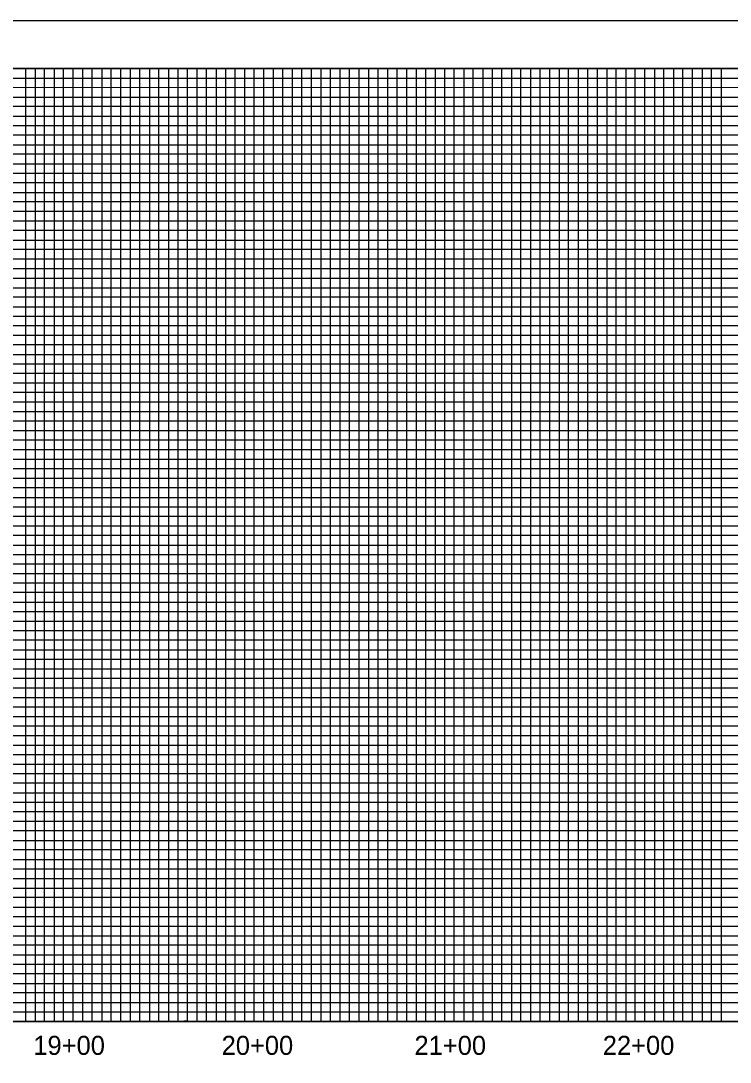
# Model space of a CAD drawing. Extents: x 502400 to 509344, y 448070 to 484209.
# Drawn here: x 506542 to 506914, y 483662 to 484209 of the extents above; entities that cross this region are included whole.
import ezdxf

# ---------------------------------------------------------------- set-up
doc = ezdxf.new("R2010")
doc.units = 0
for name, color, linetype in [('Exist Vertical Profile Vertical Axis Label', 7, 'Continuous'), ('Sheet Layout Profile Border Port 1', 7, 'Continuous'), ('Sheet Plot Border Outside CELL', 7, 'Continuous'), ('Sheet Profile CELL', 7, 'Continuous'), ('Sheet Profile Grid Major CELL', 7, 'Continuous'), ('Sheet Profile Grid Middle CELL', 7, 'Continuous'), ('Sheet Profile Grid Minor CELL', 7, 'Continuous')]:
    doc.layers.add(name, color=color, linetype=linetype)

msp = doc.modelspace()

# ---------------------------------------------------------------- linework, layer by layer
at = {"layer": 'Sheet Layout Profile Border Port 1'}
msp.add_lwpolyline([(506419.08, 484183.71), (507169.08, 484183.71), (507169.08, 483683.71), (506419.08, 483683.71)], close=True, dxfattribs=at)
at = {"layer": 'Sheet Plot Border Outside CELL'}
msp.add_lwpolyline([(505602.08, 483108.71), (507286.08, 483108.71), (507286.08, 484208.71), (505602.08, 484208.71)], close=True, dxfattribs=at)
at = {"layer": 'Sheet Profile CELL'}
msp.add_line((505769.08, 483683.71), (507269.08, 483683.71), dxfattribs=at)
msp.add_lwpolyline([(507269.08, 484183.71), (505769.08, 484183.71), (505769.08, 483133.71), (507269.08, 483133.71)], close=True, dxfattribs=at)
at = {"layer": 'Sheet Profile Grid Major CELL'}
for points in [[(506519.08, 483683.71), (506569.08, 483683.71), (506569.08, 484183.71), (506619.08, 484183.71), (506619.08, 483683.71), (506669.08, 483683.71), (506669.08, 484183.71), (506719.08, 484183.71), (506719.08, 483683.71), (506769.08, 483683.71), (506769.08, 484183.71), (506819.08, 484183.71), (506819.08, 483683.71), (506869.08, 483683.71), (506869.08, 484183.71), (506919.08, 484183.71), (506919.08, 483683.71), (506969.08, 483683.71), (506969.08, 484183.71), (507019.08, 484183.71), (507019.08, 483683.71), (507069.08, 483683.71), (507069.08, 484183.71), (507095.38, 484183.71)], [(505769.08, 484133.71), (507069.08, 484133.71)], [(507069.08, 484083.71), (505769.08, 484083.71), (505769.08, 484033.71), (507069.08, 484033.71)], [(507269.08, 483983.71), (505769.08, 483983.71), (505769.08, 483933.71), (507269.08, 483933.71)], [(507269.08, 483883.71), (505769.08, 483883.71), (505769.08, 483833.71), (507269.08, 483833.71)], [(507269.08, 483783.71), (505769.08, 483783.71), (505769.08, 483783.71), (505769.08, 483733.71), (507269.08, 483733.71)]]:
    msp.add_lwpolyline(points, dxfattribs=at)
at = {"layer": 'Sheet Profile Grid Middle CELL'}
msp.add_line((505769.08, 484158.71), (507069.03, 484158.71), dxfattribs=at)
msp.add_line((505769.08, 484158.71), (507069.03, 484158.71), dxfattribs=at)
for points in [[(506494.08, 484183.71), (506544.08, 484183.71), (506544.08, 483683.71), (506594.08, 483683.71), (506594.08, 484183.71), (506644.08, 484183.71), (506644.08, 483683.71), (506694.08, 483683.71), (506694.08, 484183.71), (506744.08, 484183.71), (506744.08, 483683.71), (506794.08, 483683.71), (506794.08, 484183.71), (506844.08, 484183.71), (506844.08, 483683.71), (506894.08, 483683.71), (506894.08, 484183.71), (506944.08, 484183.71)], [(507069.08, 484108.71), (505769.08, 484108.71), (505769.08, 484058.71), (507069.08, 484058.71)], [(507269.08, 484008.71), (505769.08, 484008.71), (505769.08, 483958.71), (507094.08, 483958.71)], [(507269.08, 483908.71), (505769.08, 483908.71), (505769.08, 483858.71), (507269.08, 483858.71)], [(507269.08, 483808.71), (505769.08, 483808.71), (505769.08, 483758.71), (507269.08, 483758.71)], [(507269.08, 483708.71), (505769.08, 483708.71)]]:
    msp.add_lwpolyline(points, dxfattribs=at)
at = {"layer": 'Sheet Profile Grid Minor CELL'}
for p, q in [((505819.08, 484178.71), (507069.08, 484178.71)), ((507069.08, 484173.71), (505819.08, 484173.36)), ((505819.08, 484168.71), (507069.08, 484168.71)), ((507069.03, 484048.71), (505819.08, 484048.71)), ((507069.08, 484043.71), (505819.08, 484043.71)), ((507069.08, 484038.71), (505819.08, 484038.71)), ((505819.08, 484028.71), (507069.08, 484028.71)), ((507069.08, 484023.71), (505819.08, 484023.71)), ((505819.08, 484018.71), (507219.08, 484018.71)), ((507219.08, 483998.71), (505819.08, 483998.71)), ((505819.08, 483993.71), (507219.08, 483993.71)), ((507219.08, 483973.71), (505819.08, 483973.71)), ((505819.08, 483968.71), (507219.08, 483968.71)), ((507219.08, 483948.71), (505819.08, 483948.71)), ((505819.08, 483943.71), (507219.08, 483943.71)), ((507219.08, 483938.71), (505819.08, 483938.71)), ((505819.08, 483928.71), (507219.08, 483928.71)), ((507219.08, 483923.71), (505819.08, 483923.71)), ((505819.08, 483918.71), (507219.08, 483918.71)), ((507219.08, 483913.71), (505819.08, 483913.71)), ((505819.08, 483903.71), (507219.08, 483903.71)), ((507219.08, 483898.71), (505819.08, 483898.71)), ((505819.08, 483893.71), (507219.08, 483893.71)), ((507219.08, 483888.71), (505819.08, 483888.71)), ((505819.08, 483878.71), (507219.08, 483878.71)), ((507219.08, 483873.71), (505819.08, 483873.71)), ((505819.08, 483868.71), (507219.08, 483868.71)), ((507219.08, 483863.71), (505819.08, 483863.71)), ((505819.08, 483853.71), (507219.08, 483853.71)), ((507219.08, 483848.71), (505819.08, 483848.71)), ((505819.08, 483843.71), (507219.08, 483843.71)), ((507219.08, 483838.71), (505819.08, 483838.71)), ((505819.08, 483828.71), (507219.08, 483828.71)), ((507219.08, 483823.71), (505819.08, 483823.71)), ((505819.08, 483818.71), (507219.08, 483818.71)), ((507219.08, 483813.71), (505819.08, 483813.71)), ((505819.08, 483803.71), (507219.08, 483803.71)), ((507219.08, 483798.71), (505819.08, 483798.71)), ((507219.08, 483793.71), (505819.08, 483793.71)), ((507219.08, 483788.71), (505819.08, 483788.71)), ((505819.08, 483778.71), (507219.08, 483778.71)), ((507219.08, 483773.71), (505819.08, 483773.71)), ((505819.08, 483768.71), (507219.08, 483768.71)), ((507219.08, 483763.71), (505819.08, 483763.71)), ((505819.08, 483753.71), (507219.08, 483753.71)), ((507219.08, 483748.71), (505819.08, 483748.71)), ((505819.08, 483743.71), (507219.08, 483743.71)), ((507219.08, 483738.71), (505819.08, 483738.71)), ((505819.08, 483728.71), (507219.08, 483728.71)), ((507219.08, 483723.71), (505819.08, 483723.71)), ((505819.08, 483718.71), (507219.08, 483718.71)), ((507219.08, 483713.71), (505819.08, 483713.71)), ((505819.08, 483703.71), (507219.08, 483703.71)), ((507219.08, 483698.71), (505819.08, 483698.71)), ((505819.08, 483693.71), (507219.08, 483693.71))]:
    msp.add_line(p, q, dxfattribs=at)
for points in [[(506539.08, 484183.71), (506549.08, 484183.71), (506549.08, 483683.71), (506554.08, 483683.71), (506554.08, 484183.71), (506559.08, 484183.71), (506559.08, 483683.71), (506564.08, 483683.71), (506564.08, 484183.71), (506574.08, 484183.71), (506574.08, 483683.71), (506579.08, 483683.71), (506579.08, 484183.71), (506584.08, 484183.71), (506584.08, 483683.71), (506589.08, 483683.71), (506589.08, 484183.71), (506599.08, 484183.71), (506599.08, 483683.71), (506604.08, 483683.71), (506604.08, 484183.71), (506609.08, 484183.71), (506609.08, 483683.71), (506614.08, 483683.71), (506614.08, 484183.71), (506624.08, 484183.71), (506624.08, 483683.71), (506628.78, 483684.26), (506629.08, 483683.71), (506629.08, 484183.71), (506634.08, 484183.71), (506634.08, 483683.71), (506639.08, 483683.71), (506639.08, 484183.71), (506649.08, 484183.71), (506649.08, 483683.71), (506654.08, 483683.71)], [(506654.08, 483683.71), (506654.08, 484183.71), (506659.08, 484183.71), (506659.08, 483683.71), (506664.08, 483683.71), (506664.08, 484183.71), (506674.08, 484183.71), (506674.08, 483683.71), (506679.08, 483683.71), (506679.08, 484183.71), (506684.08, 484183.71), (506684.08, 483683.71), (506689.08, 483683.71), (506689.08, 484183.71), (506699.08, 484183.71), (506699.08, 483683.71), (506704.08, 483683.71), (506704.08, 484183.71), (506709.08, 484183.71), (506709.08, 483683.71), (506714.08, 483683.71), (506714.08, 484183.71), (506724.08, 484183.71), (506724.08, 483683.71), (506729.08, 483683.71), (506729.08, 484183.71), (506734.08, 484183.71), (506734.08, 483683.71), (506739.08, 483683.71), (506739.08, 484183.71), (506749.08, 484183.71), (506749.08, 483683.71), (506754.08, 483683.71), (506754.08, 484183.71), (506759.08, 484183.71), (506759.08, 483683.71), (506764.08, 483683.71), (506764.08, 484183.71), (506774.08, 484183.71), (506774.08, 483683.71), (506779.08, 483683.71), (506779.08, 484183.71), (506784.08, 484183.71), (506784.08, 483683.71), (506789.08, 483683.71), (506789.08, 484183.71), (506799.08, 484183.71), (506799.08, 483683.71), (506804.08, 483683.71), (506804.08, 484183.71), (506809.08, 484183.71), (506809.08, 483683.71), (506814.08, 483683.71), (506814.08, 484183.71), (506824.08, 484183.71), (506824.08, 483683.71), (506829.08, 483683.71), (506829.08, 484183.71), (506834.08, 484183.71), (506834.08, 483683.71), (506839.08, 483683.71), (506839.08, 484183.71), (506849.08, 484183.71), (506849.08, 483683.71), (506854.08, 483683.71), (506854.08, 484183.71), (506859.08, 484183.71), (506859.08, 483683.71), (506864.08, 483683.71), (506864.08, 484183.71), (506874.08, 484183.71), (506874.08, 483683.71), (506879.08, 483683.71), (506879.08, 484183.71), (506884.08, 484183.71), (506884.08, 483683.71), (506889.08, 483683.71), (506889.08, 484183.71), (506899.08, 484183.71), (506899.08, 483683.71), (506904.08, 483683.71), (506904.08, 484183.71), (506909.08, 484183.71), (506909.08, 483683.71), (506914.08, 483683.71)], [(507069.08, 484163.71), (505819.08, 484163.71), (505819.08, 484153.71), (507069.08, 484153.71)], [(507069.03, 484148.71), (505819.08, 484148.71), (505819.08, 484143.71), (507069.08, 484143.71)], [(507069.08, 484138.71), (505819.08, 484138.71), (505819.08, 484128.71), (507069.08, 484128.71)], [(507069.08, 484123.71), (505819.08, 484123.71), (505819.08, 484118.71), (507069.08, 484118.71)], [(507069.08, 484113.71), (505819.08, 484113.71), (505819.08, 484103.71), (507069.08, 484103.71)], [(507069.08, 484098.71), (505819.08, 484098.71), (505819.08, 484093.71), (507069.08, 484093.71)], [(507069.08, 484088.71), (505819.08, 484088.71), (505819.08, 484078.71), (507069.08, 484078.71)], [(507069.08, 484073.61), (505819.18, 484073.61), (505819.18, 484068.71), (507069.08, 484068.71)], [(507069.08, 484063.71), (505819.08, 484063.71), (505819.08, 484053.71), (507069.08, 484053.71)], [(507219.08, 484013.71), (505819.08, 484013.71), (505819.08, 484003.71), (507219.08, 484003.71)], [(507219.08, 483988.71), (505819.08, 483988.71), (505819.08, 483978.71), (507219.08, 483978.71)], [(507219.08, 483963.71), (505819.08, 483963.71), (505819.08, 483953.71), (507219.08, 483953.71)], [(507219.08, 483688.71), (505819.08, 483688.71)]]:
    msp.add_lwpolyline(points, dxfattribs=at)

# ---------------------------------------------------------------- texts
at = {"layer": 'Exist Vertical Profile Vertical Axis Label'}
for s, p in [('19+00', (506548.21, 483666.21)), ('20+00', (506647.01, 483666.21)), ('21+00', (506748.21, 483666.21)), ('22+00', (506847.01, 483666.21))]:
    msp.add_text(s, height=10, dxfattribs=at).set_placement(p)

doc.saveas('drawing.dxf')
